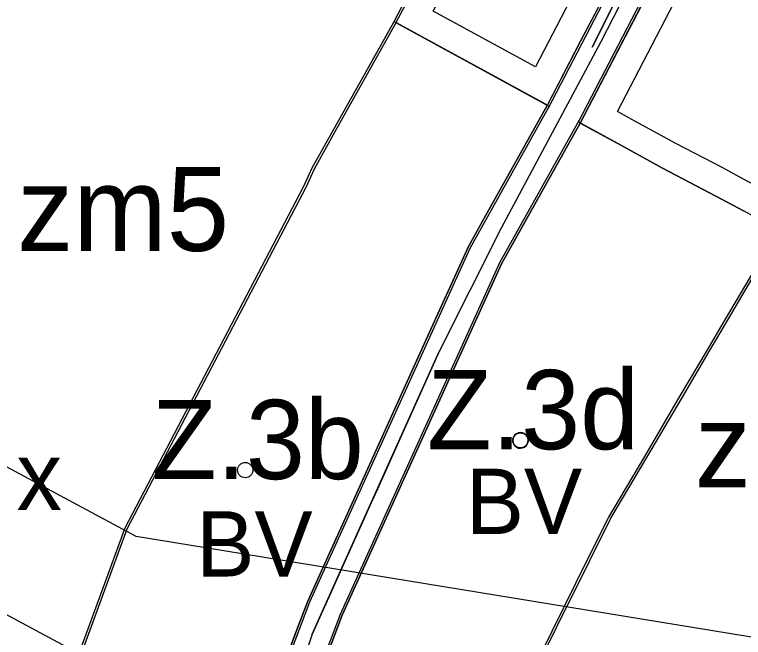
# Model space of a CAD drawing. Extents: x -555070 to -553076, y -1186731 to -1182766.
# Drawn here: x -554895.6 to -554739.3, y -1185432.6 to -1185299 of the extents above; entities that cross this region are included whole.
import ezdxf

# ---------------------------------------------------------------- set-up
doc = ezdxf.new("R2010")
doc.units = 0
for name, color, linetype in [('HRANICE_ZMENY_DO_KOO', 7, 'Continuous'), ('Level 10', 7, 'Continuous'), ('Level 13', 7, 'Continuous'), ('Level 29', 7, 'Continuous'), ('Level 4', 7, 'Continuous'), ('Level 46', 7, 'Continuous'), ('Level 56', 7, 'Continuous'), ('Level 6', 7, 'Continuous'), ('Level 63', 7, 'Continuous'), ('navrh_BV', 7, 'Continuous'), ('OBRYS_PLOCH', 7, 'Continuous'), ('rezerva_BV', 7, 'Continuous'), ('stav_PU', 7, 'Continuous')]:
    doc.layers.add(name, color=color, linetype=linetype)

msp = doc.modelspace()

# ---------------------------------------------------------------- linework, layer by layer
at = {"layer": 'HRANICE_ZMENY_DO_KOO'}
msp.add_line((-554814.11, -1185300.6), (-554780.9, -1185318.72), dxfattribs=at)
for points in [[(-554781.14, -1185319.16), (-554749.64, -1185258.53), (-554735.45, -1185228.43), (-554735.94, -1185228.17), (-554732.88, -1185222.18), (-554722.28, -1185200.47), (-554716.89, -1185189.03), (-554695.6, -1185133.26), (-554681.28, -1185085.12), (-554676.85, -1185071.58), (-554673.03, -1185055.54), (-554678.3, -1185053.24), (-554698.85, -1185044.53), (-554707.52, -1185040.87), (-554718.97, -1185084), (-554731.8, -1185124.46), (-554753.51, -1185179), (-554769.31, -1185211.12), (-554783.7, -1185241.67), (-554814.38, -1185300.72)], [(-554739.32, -1185253.05), (-554743.37, -1185261.64), (-554774.76, -1185322.08)], [(-554814.38, -1185300.72), (-554831.83, -1185331.98), (-554833.63, -1185335.93), (-554871.99, -1185409.18), (-554894.99, -1185471.93), (-554889.09, -1185474.59), (-554852.66, -1185483.58), (-554847.83, -1185465.96), (-554832.28, -1185424.99), (-554797.88, -1185349.12), (-554780.92, -1185318.75), (-554780.9, -1185318.71)], [(-554774.52, -1185321.65), (-554791.63, -1185352.27), (-554825.81, -1185427.68), (-554841.17, -1185468.13), (-554846.04, -1185485.92), (-554835.12, -1185481.76), (-554812.31, -1185473.07), (-554804.43, -1185470.07), (-554795.94, -1185466.83), (-554789.52, -1185451.86), (-554789.52, -1185451.86), (-554786.52, -1185444.87), (-554772.24, -1185416.15), (-554767.7, -1185407.07), (-554760.02, -1185394.04)], [(-554731.33, -1185345.43), (-554739.23, -1185341.16), (-554741.42, -1185340.01), (-554746.53, -1185337.24), (-554756.64, -1185331.95), (-554765.45, -1185327.15), (-554774.75, -1185322.07)], [(-554760.02, -1185394.04), (-554752.38, -1185381.08), (-554746.62, -1185371.31), (-554744.12, -1185367.07), (-554741.75, -1185363.06), (-554734.45, -1185350.67), (-554731.1, -1185344.99)]]:
    msp.add_lwpolyline(points, dxfattribs=at)
at = {"layer": 'Level 13'}
for p, q in [((-554742.92, -1185261.86), (-554774.32, -1185322.31)), ((-554774.2, -1185304.73), (-554759.23, -1185275.9)), ((-554807.06, -1185287.73), (-554813.83, -1185300.75)), ((-554813.94, -1185300.96), (-554826.92, -1185324.2)), ((-554813.83, -1185300.75), (-554813.94, -1185300.96)), ((-554813.83, -1185300.75), (-554781.34, -1185318.48)), ((-554781.34, -1185318.48), (-554813.83, -1185300.75)), ((-554781.34, -1185318.48), (-554774.2, -1185304.73)), ((-554794.88, -1185342.72), (-554781.36, -1185318.51)), ((-554781.36, -1185318.51), (-554781.34, -1185318.48)), ((-554774.32, -1185322.31), (-554791.18, -1185352.5)), ((-554765.45, -1185327.15), (-554774.32, -1185322.31)), ((-554774.32, -1185322.31), (-554765.45, -1185327.15)), ((-554826.92, -1185324.2), (-554831.39, -1185332.2)), ((-554756.64, -1185331.95), (-554765.45, -1185327.15)), ((-554765.45, -1185327.15), (-554756.64, -1185331.95)), ((-554831.39, -1185332.2), (-554833.18, -1185336.15)), ((-554746.53, -1185337.24), (-554756.64, -1185331.95)), ((-554756.64, -1185331.95), (-554746.53, -1185337.24)), ((-554833.18, -1185336.15), (-554871.53, -1185409.38)), ((-554741.42, -1185340.01), (-554746.53, -1185337.24)), ((-554746.53, -1185337.24), (-554741.42, -1185340.01)), ((-554739.23, -1185341.16), (-554741.42, -1185340.01)), ((-554741.42, -1185340.01), (-554739.23, -1185341.16)), ((-554798.33, -1185348.89), (-554794.88, -1185342.72)), ((-554807.68, -1185369.52), (-554798.33, -1185348.89)), ((-554742.18, -1185362.81), (-554734.88, -1185350.42)), ((-554791.18, -1185352.5), (-554825.35, -1185427.87)), ((-554744.55, -1185366.82), (-554742.18, -1185362.81)), ((-554747.05, -1185371.06), (-554744.55, -1185366.82)), ((-554823.22, -1185403.79), (-554807.68, -1185369.52)), ((-554752.81, -1185380.83), (-554747.05, -1185371.06)), ((-554760.45, -1185393.79), (-554752.81, -1185380.83)), ((-554768.14, -1185406.83), (-554760.45, -1185393.79)), ((-554829.45, -1185417.54), (-554823.22, -1185403.79)), ((-554772.69, -1185415.93), (-554768.14, -1185406.83)), ((-554871.53, -1185409.38), (-554894.36, -1185471.66)), ((-554786.97, -1185444.66), (-554772.69, -1185415.93)), ((-554832.74, -1185424.8), (-554829.45, -1185417.54)), ((-554834.79, -1185430.19), (-554832.74, -1185424.8)), ((-554825.35, -1185427.87), (-554840.69, -1185468.29)), ((-554848.3, -1185465.81), (-554834.79, -1185430.19))]:
    msp.add_line(p, q, dxfattribs=at)
at = {"layer": 'Level 29'}
for points in [[(-554293.2, -1185505.39), (-554587.17, -1185457.18), (-554869.52, -1185410.99), (-555057.83, -1185309.87), (-555060.53, -1185308.42)], [(-555065.37, -1185337.55), (-554878.61, -1185437.76), (-554591.7, -1185484.82), (-554218.96, -1185545.93), (-553901.49, -1185597.94), (-553620.76, -1185643.99), (-553313.81, -1185694.25), (-553085.95, -1185731.63)]]:
    msp.add_lwpolyline(points, dxfattribs=at)
at = {"layer": 'Level 4'}
for centre in [(-554787.11, -1185390.4), (-554787.11, -1185390.4), (-554787.09, -1185390.32), (-554846.15, -1185396.73)]:
    msp.add_circle(centre, 1.64, dxfattribs=at)
at = {"layer": 'Level 56'}
for p, q in [((-554813.94, -1185300.96), (-554826.92, -1185324.2)), ((-554813.83, -1185300.75), (-554813.94, -1185300.96)), ((-554781.34, -1185318.48), (-554813.83, -1185300.75)), ((-554774.32, -1185322.31), (-554791.18, -1185352.5)), ((-554826.92, -1185324.2), (-554831.39, -1185332.2)), ((-554831.39, -1185332.2), (-554833.18, -1185336.15)), ((-554746.53, -1185337.24), (-554756.64, -1185331.95)), ((-554833.18, -1185336.15), (-554871.53, -1185409.38)), ((-554798.33, -1185348.89), (-554794.88, -1185342.72)), ((-554807.68, -1185369.52), (-554798.33, -1185348.89)), ((-554742.18, -1185362.81), (-554734.88, -1185350.42)), ((-554791.18, -1185352.5), (-554825.35, -1185427.87)), ((-554744.55, -1185366.82), (-554742.18, -1185362.81)), ((-554747.05, -1185371.06), (-554744.55, -1185366.82)), ((-554823.22, -1185403.79), (-554807.68, -1185369.52)), ((-554752.81, -1185380.83), (-554747.05, -1185371.06)), ((-554760.45, -1185393.79), (-554752.81, -1185380.83)), ((-554768.14, -1185406.83), (-554760.45, -1185393.79)), ((-554829.45, -1185417.54), (-554823.22, -1185403.79)), ((-554772.69, -1185415.93), (-554768.14, -1185406.83)), ((-554871.53, -1185409.38), (-554894.36, -1185471.66)), ((-554786.97, -1185444.66), (-554772.69, -1185415.93)), ((-554832.74, -1185424.8), (-554829.45, -1185417.54)), ((-554834.79, -1185430.19), (-554832.74, -1185424.8)), ((-554825.35, -1185427.87), (-554840.69, -1185468.29)), ((-554848.3, -1185465.81), (-554834.79, -1185430.19))]:
    msp.add_line(p, q, dxfattribs=at)
for points in [[(-554794.88, -1185342.72), (-554781.36, -1185318.51), (-554781.34, -1185318.48)], [(-554756.64, -1185331.95), (-554765.45, -1185327.15), (-554774.32, -1185322.31)], [(-554739.23, -1185341.16), (-554741.42, -1185340.01), (-554746.53, -1185337.24)]]:
    msp.add_lwpolyline(points, dxfattribs=at)
at = {"layer": 'Level 6'}
for points in [[(-554732.53, -1185230.74), (-554748.07, -1185262.32), (-554769.87, -1185304.87)], [(-554769.87, -1185304.87), (-554791.22, -1185344.83), (-554804.53, -1185371.26), (-554831.78, -1185431.89), (-554849.33, -1185483.99), (-554852.65, -1185494.03)]]:
    msp.add_lwpolyline(points, dxfattribs=at)
at = {"layer": 'navrh_BV'}
for p, q in [((-554813.94, -1185300.96), (-554826.92, -1185324.2)), ((-554813.94, -1185300.96), (-554826.92, -1185324.2)), ((-554813.83, -1185300.75), (-554813.94, -1185300.96)), ((-554813.83, -1185300.75), (-554813.94, -1185300.96)), ((-554781.34, -1185318.48), (-554813.83, -1185300.75)), ((-554781.34, -1185318.48), (-554813.83, -1185300.75)), ((-554794.88, -1185342.72), (-554781.36, -1185318.51)), ((-554794.88, -1185342.72), (-554781.36, -1185318.51)), ((-554781.36, -1185318.51), (-554781.34, -1185318.48)), ((-554781.36, -1185318.51), (-554781.34, -1185318.48)), ((-554774.32, -1185322.31), (-554791.18, -1185352.5)), ((-554774.32, -1185322.31), (-554791.18, -1185352.5)), ((-554765.45, -1185327.15), (-554774.32, -1185322.31)), ((-554765.45, -1185327.15), (-554774.32, -1185322.31)), ((-554756.64, -1185331.95), (-554765.45, -1185327.15)), ((-554756.64, -1185331.95), (-554765.45, -1185327.15)), ((-554746.53, -1185337.24), (-554756.64, -1185331.95)), ((-554746.53, -1185337.24), (-554756.64, -1185331.95)), ((-554833.18, -1185336.15), (-554871.53, -1185409.38)), ((-554833.18, -1185336.15), (-554871.53, -1185409.38)), ((-554741.42, -1185340.01), (-554746.53, -1185337.24)), ((-554741.42, -1185340.01), (-554746.53, -1185337.24)), ((-554739.23, -1185341.16), (-554741.42, -1185340.01)), ((-554739.23, -1185341.16), (-554741.42, -1185340.01)), ((-554798.33, -1185348.89), (-554794.88, -1185342.72)), ((-554798.33, -1185348.89), (-554794.88, -1185342.72)), ((-554807.68, -1185369.52), (-554798.33, -1185348.89)), ((-554807.68, -1185369.52), (-554798.33, -1185348.89)), ((-554742.18, -1185362.81), (-554734.88, -1185350.42)), ((-554742.18, -1185362.81), (-554734.88, -1185350.42)), ((-554791.18, -1185352.5), (-554825.35, -1185427.87)), ((-554791.18, -1185352.5), (-554825.35, -1185427.87)), ((-554744.55, -1185366.82), (-554742.18, -1185362.81)), ((-554744.55, -1185366.82), (-554742.18, -1185362.81)), ((-554747.05, -1185371.06), (-554744.55, -1185366.82)), ((-554747.05, -1185371.06), (-554744.55, -1185366.82)), ((-554823.22, -1185403.79), (-554807.68, -1185369.52)), ((-554823.22, -1185403.79), (-554807.68, -1185369.52)), ((-554752.81, -1185380.83), (-554747.05, -1185371.06)), ((-554760.45, -1185393.79), (-554752.81, -1185380.83)), ((-554768.14, -1185406.83), (-554760.45, -1185393.79)), ((-554768.14, -1185406.83), (-554760.45, -1185393.79)), ((-554829.45, -1185417.54), (-554823.22, -1185403.79)), ((-554829.45, -1185417.54), (-554823.22, -1185403.79)), ((-554772.69, -1185415.93), (-554768.14, -1185406.83)), ((-554772.69, -1185415.93), (-554768.14, -1185406.83)), ((-554786.97, -1185444.66), (-554772.69, -1185415.93)), ((-554786.97, -1185444.66), (-554772.69, -1185415.93)), ((-554832.74, -1185424.8), (-554829.45, -1185417.54)), ((-554834.79, -1185430.19), (-554832.74, -1185424.8)), ((-554825.35, -1185427.87), (-554840.69, -1185468.29)), ((-554825.35, -1185427.87), (-554840.69, -1185468.29)), ((-554848.3, -1185465.81), (-554834.79, -1185430.19)), ((-554848.3, -1185465.81), (-554834.79, -1185430.19))]:
    msp.add_line(p, q, dxfattribs=at)
for points in [[(-554826.92, -1185324.2), (-554831.39, -1185332.2), (-554833.18, -1185336.15)], [(-554826.92, -1185324.2), (-554831.39, -1185332.2), (-554833.18, -1185336.15)], [(-554760.45, -1185393.79), (-554752.81, -1185380.83), (-554747.05, -1185371.06)], [(-554871.53, -1185409.38), (-554894.36, -1185471.66), (-554888.92, -1185474.12)], [(-554871.53, -1185409.38), (-554894.36, -1185471.66), (-554888.92, -1185474.12)], [(-554834.79, -1185430.19), (-554832.74, -1185424.8), (-554829.45, -1185417.54)]]:
    msp.add_lwpolyline(points, dxfattribs=at)
for centre, start, end in [((-554787.09, -1185390.32), 344.6415, 167.2575), ((-554787.09, -1185390.32), 344.6415, 167.2575), ((-554787.11, -1185390.4), 164.6415, 347.2575), ((-554787.11, -1185390.4), 164.6415, 347.2575)]:
    msp.add_arc(centre, 1.64, start, end, dxfattribs=at)
at = {"layer": 'OBRYS_PLOCH'}
for p, q in [((-554774.32, -1185322.31), (-554742.92, -1185261.86)), ((-554774.32, -1185322.31), (-554742.92, -1185261.86)), ((-554759.23, -1185275.9), (-554774.2, -1185304.73)), ((-554759.23, -1185275.9), (-554774.2, -1185304.73)), ((-554813.94, -1185300.96), (-554826.92, -1185324.2)), ((-554813.83, -1185300.75), (-554813.94, -1185300.96)), ((-554781.34, -1185318.48), (-554813.83, -1185300.75)), ((-554774.2, -1185304.73), (-554781.36, -1185318.51)), ((-554781.36, -1185318.51), (-554794.88, -1185342.72)), ((-554794.88, -1185342.72), (-554781.36, -1185318.51)), ((-554781.36, -1185318.51), (-554781.34, -1185318.48)), ((-554791.18, -1185352.5), (-554774.32, -1185322.31)), ((-554791.18, -1185352.5), (-554774.32, -1185322.31)), ((-554774.32, -1185322.31), (-554791.18, -1185352.5)), ((-554765.45, -1185327.15), (-554774.32, -1185322.31)), ((-554826.92, -1185324.2), (-554831.39, -1185332.2)), ((-554756.64, -1185331.95), (-554765.45, -1185327.15)), ((-554831.39, -1185332.2), (-554833.18, -1185336.15)), ((-554746.53, -1185337.24), (-554756.64, -1185331.95)), ((-554833.18, -1185336.15), (-554871.53, -1185409.38)), ((-554741.42, -1185340.01), (-554746.53, -1185337.24)), ((-554739.23, -1185341.16), (-554741.42, -1185340.01)), ((-554798.33, -1185348.89), (-554794.88, -1185342.72)), ((-554807.68, -1185369.52), (-554798.33, -1185348.89)), ((-554742.18, -1185362.81), (-554734.88, -1185350.42)), ((-554825.35, -1185427.87), (-554791.18, -1185352.5)), ((-554825.35, -1185427.87), (-554791.18, -1185352.5)), ((-554791.18, -1185352.5), (-554825.35, -1185427.87)), ((-554744.55, -1185366.82), (-554742.18, -1185362.81)), ((-554747.05, -1185371.06), (-554744.55, -1185366.82)), ((-554807.68, -1185369.52), (-554823.22, -1185403.79)), ((-554807.68, -1185369.52), (-554823.22, -1185403.79)), ((-554823.22, -1185403.79), (-554807.68, -1185369.52)), ((-554768.14, -1185406.83), (-554760.45, -1185393.79)), ((-554823.22, -1185403.79), (-554829.45, -1185417.54)), ((-554823.22, -1185403.79), (-554829.45, -1185417.54)), ((-554829.45, -1185417.54), (-554823.22, -1185403.79)), ((-554772.69, -1185415.93), (-554768.14, -1185406.83)), ((-554871.53, -1185409.38), (-554894.36, -1185471.66)), ((-554786.97, -1185444.66), (-554772.69, -1185415.93)), ((-554829.45, -1185417.54), (-554832.74, -1185424.8)), ((-554832.74, -1185424.8), (-554829.45, -1185417.54)), ((-554832.74, -1185424.8), (-554834.79, -1185430.19)), ((-554834.79, -1185430.19), (-554832.74, -1185424.8)), ((-554840.69, -1185468.29), (-554825.35, -1185427.87)), ((-554840.69, -1185468.29), (-554825.35, -1185427.87)), ((-554825.35, -1185427.87), (-554840.69, -1185468.29)), ((-554834.79, -1185430.19), (-554848.3, -1185465.81)), ((-554834.79, -1185430.19), (-554848.3, -1185465.81)), ((-554848.3, -1185465.81), (-554834.79, -1185430.19))]:
    msp.add_line(p, q, dxfattribs=at)
for points in [[(-554774.2, -1185304.73), (-554781.36, -1185318.51), (-554794.88, -1185342.72)], [(-554794.88, -1185342.72), (-554798.33, -1185348.89), (-554807.68, -1185369.52)], [(-554794.88, -1185342.72), (-554798.33, -1185348.89), (-554807.68, -1185369.52)], [(-554760.45, -1185393.79), (-554752.81, -1185380.83), (-554747.05, -1185371.06)], [(-554829.45, -1185417.54), (-554832.74, -1185424.8), (-554834.79, -1185430.19)]]:
    msp.add_lwpolyline(points, dxfattribs=at)
at = {"layer": 'rezerva_BV'}
for p, q in [((-554742.92, -1185261.86), (-554774.32, -1185322.31)), ((-554742.92, -1185261.86), (-554774.32, -1185322.31)), ((-554774.2, -1185304.73), (-554759.23, -1185275.9)), ((-554774.2, -1185304.73), (-554759.23, -1185275.9)), ((-554807.06, -1185287.73), (-554813.83, -1185300.75)), ((-554807.06, -1185287.73), (-554813.83, -1185300.75)), ((-554813.83, -1185300.75), (-554781.34, -1185318.48)), ((-554813.83, -1185300.75), (-554781.34, -1185318.48)), ((-554781.34, -1185318.48), (-554774.2, -1185304.73)), ((-554781.34, -1185318.48), (-554774.2, -1185304.73)), ((-554743.71, -1185331.94), (-554753.81, -1185326.66)), ((-554756.64, -1185331.95), (-554746.53, -1185337.24)), ((-554756.64, -1185331.95), (-554746.53, -1185337.24)), ((-554746.53, -1185337.24), (-554741.42, -1185340.01)), ((-554746.53, -1185337.24), (-554741.42, -1185340.01)), ((-554741.42, -1185340.01), (-554739.23, -1185341.16)), ((-554741.42, -1185340.01), (-554739.23, -1185341.16))]:
    msp.add_line(p, q, dxfattribs=at)
for points in [[(-554755.47, -1185255.65), (-554783.85, -1185310.28), (-554805.8, -1185298.3), (-554777.88, -1185244.55), (-554763.45, -1185213.94), (-554747.57, -1185181.64), (-554725.82, -1185127.02), (-554704.58, -1185138.55), (-554722.87, -1185186.48), (-554728.14, -1185197.66), (-554738.8, -1185219.49), (-554741.6, -1185226.21), (-554755.47, -1185255.65)], [(-554766.29, -1185319.86), (-554737.54, -1185264.52), (-554704.46, -1185194.32)], [(-554753.81, -1185326.66), (-554762.58, -1185321.88), (-554766.29, -1185319.86)], [(-554774.32, -1185322.31), (-554765.45, -1185327.15), (-554756.64, -1185331.95)], [(-554774.32, -1185322.31), (-554765.45, -1185327.15), (-554756.64, -1185331.95)], [(-554736.41, -1185335.86), (-554738.6, -1185334.72), (-554743.71, -1185331.94)]]:
    msp.add_lwpolyline(points, dxfattribs=at)
at = {"layer": 'stav_PU'}
for p, q in [((-554774.32, -1185322.31), (-554742.92, -1185261.86)), ((-554774.32, -1185322.31), (-554742.92, -1185261.86)), ((-554759.23, -1185275.9), (-554774.2, -1185304.73)), ((-554759.23, -1185275.9), (-554774.2, -1185304.73)), ((-554771.69, -1185306.03), (-554757.18, -1185276.99)), ((-554764, -1185290.64), (-554771.69, -1185306.03)), ((-554791.18, -1185352.5), (-554774.32, -1185322.31)), ((-554791.18, -1185352.5), (-554774.32, -1185322.31)), ((-554825.35, -1185427.87), (-554791.18, -1185352.5)), ((-554825.35, -1185427.87), (-554791.18, -1185352.5)), ((-554807.68, -1185369.52), (-554823.22, -1185403.79)), ((-554807.68, -1185369.52), (-554823.22, -1185403.79)), ((-554819.98, -1185405.63), (-554804.53, -1185371.26)), ((-554804.53, -1185371.26), (-554811.49, -1185386.76)), ((-554811.49, -1185386.76), (-554817.8, -1185400.8)), ((-554817.8, -1185400.8), (-554819.98, -1185405.63)), ((-554823.22, -1185403.79), (-554829.45, -1185417.54)), ((-554823.22, -1185403.79), (-554829.45, -1185417.54)), ((-554825.61, -1185418.17), (-554819.98, -1185405.63)), ((-554819.98, -1185405.63), (-554823.62, -1185413.75)), ((-554829.45, -1185417.54), (-554832.74, -1185424.8)), ((-554831.78, -1185431.89), (-554825.61, -1185418.17)), ((-554832.74, -1185424.8), (-554834.79, -1185430.19)), ((-554840.69, -1185468.29), (-554825.35, -1185427.87)), ((-554840.69, -1185468.29), (-554825.35, -1185427.87)), ((-554834.79, -1185430.19), (-554848.3, -1185465.81)), ((-554834.79, -1185430.19), (-554848.3, -1185465.81))]:
    msp.add_line(p, q, dxfattribs=at)
for points in [[(-554774.2, -1185304.73), (-554781.36, -1185318.51), (-554794.88, -1185342.72)], [(-554774.2, -1185304.73), (-554781.36, -1185318.51), (-554794.88, -1185342.72)], [(-554794.88, -1185342.72), (-554798.33, -1185348.89), (-554807.68, -1185369.52)], [(-554794.88, -1185342.72), (-554798.33, -1185348.89), (-554807.68, -1185369.52)], [(-554823.62, -1185413.75), (-554828.21, -1185423.96), (-554831.78, -1185431.89)], [(-554829.45, -1185417.54), (-554832.74, -1185424.8), (-554834.79, -1185430.19)]]:
    msp.add_lwpolyline(points, dxfattribs=at)

# ---------------------------------------------------------------- texts
at = {"layer": 'Level 10'}
for s, p in [('zm5', (-554895.07, -1185349.73)), ('zm7', (-554749.7, -1185400.44))]:
    msp.add_text(s, height=18, dxfattribs=at).set_placement(p)
at = {"layer": 'Level 29'}
msp.add_text('x', height=14.62, rotation=0.008, dxfattribs=at).set_placement((-554895.24, -1185405.32))
at = {"layer": 'Level 46'}
for s, p in [('Z.3d', (-554807.15, -1185392.26)), ('Z.3d', (-554807.15, -1185392.26)), ('Z.3b', (-554866.2, -1185398.66))]:
    msp.add_text(s, height=17, dxfattribs=at).set_placement(p)
at = {"layer": 'Level 63'}
for p in [(-554798.84, -1185410.43), (-554798.84, -1185410.43), (-554798.84, -1185410.43), (-554856.66, -1185419.55)]:
    msp.add_text('BV', height=14, dxfattribs=at).set_placement(p)

doc.saveas('drawing.dxf')
